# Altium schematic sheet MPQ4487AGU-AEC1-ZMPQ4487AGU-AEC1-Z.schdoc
size 127 x 101 mm
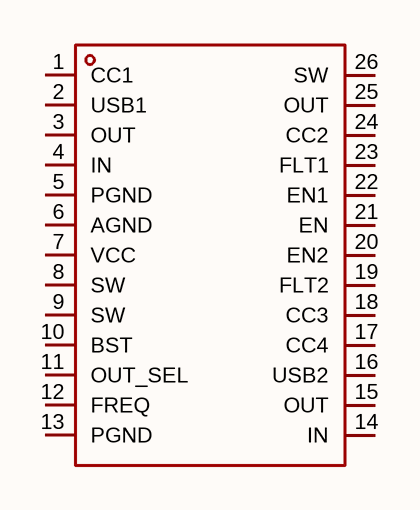
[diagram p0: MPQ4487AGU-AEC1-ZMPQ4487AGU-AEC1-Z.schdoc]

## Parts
U?  mpq4487agu-aec1-z  [QFN-26_L5.0-W5.0_MPQ4488GU]  (value not drawn)

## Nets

Not connected (* = marked no-connect by the designer): U? 1(CC1) 2(USB1) 3(OUT) 4(IN) 5(PGND) 6(AGND) 7(VCC) 8(SW) 9(SW) 10(BST) 11(OUT_SEL) 12(FREQ) 13(PGND) 14(IN) 15(OUT) 16(USB2) 17(CC4) 18(CC3) 19(FLT2) 20(EN2) 21(EN) 22(EN1) 23(FLT1) 24(CC2) 25(OUT) 26(SW)

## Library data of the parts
U? = mpq4487agu-aec1-z: 功能类型:降压型;工作电压:6V~36V;输出电压:5.17V；5.3V；5.1V;输出电流:6A;输出类型:固定;; Manufacturer: MPS(芯源); AddInBom: yes; ModelId: c2a6ca9f90434d41a5f389e6427afba1; ModelTransform: 197.6374,197.6374,0,0,0,0,0,0,0; Function: 降压型; Voltage - Supply: 6V~36V; Output Current: 6A; Frequency - Switching: 450kHz; Synchronous Rectifier: 是; Number of Outputs: 1; Topology: 降压式; Quiescent Current: 400uA; Switch tube (built-in/external): 内置; Output Type: 固定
